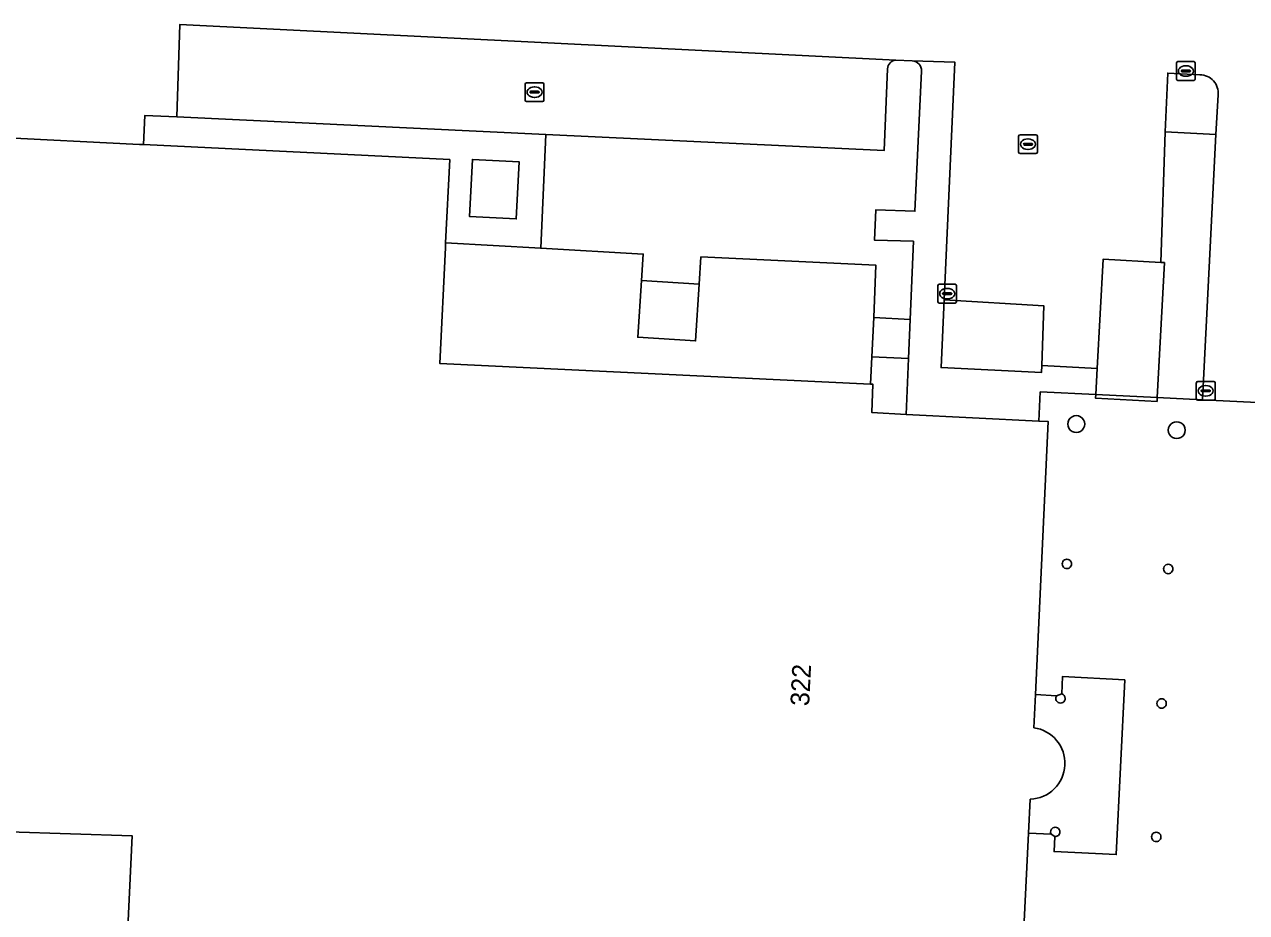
# Model space of a CAD drawing. Extents: x 161090 to 161692, y 379509 to 380907.
# Drawn here: x 161388.6 to 161453.8, y 379714.5 to 379761.9 of the extents above; entities that cross this region are included whole.
import ezdxf

# ---------------------------------------------------------------- set-up
doc = ezdxf.new("R2010")
doc.units = 0
for name, color, linetype in [('IMGEO_Erf', 7, 'Continuous'), ('IMGEO_Groenvoorziening', 7, 'Continuous'), ('IMGEO_Haag', 7, 'Continuous'), ('IMGEO_Hek', 7, 'Continuous'), ('IMGEO_Kolk', 7, 'Continuous'), ('IMGEO_Lage_trafo', 7, 'Continuous'), ('IMGEO_Pand', 7, 'Continuous'), ('IMGEO_Pand_nummerreeks', 7, 'Continuous'), ('IMGEO_Pand_overbouw', 7, 'Continuous'), ('IMGEO_Parkeervlak_gesloten', 7, 'Continuous'), ('IMGEO_Parkeervlak_open', 7, 'Continuous'), ('IMGEO_Rijbaan_lokaal_gesloten', 7, 'Continuous'), ('IMGEO_Rioolput', 7, 'Continuous'), ('IMGEO_Terreindeel_open', 7, 'Continuous'), ('IMGEO_Voetpad_gesloten', 7, 'Continuous'), ('IMGEO_Voetpad_op_trap', 7, 'Continuous'), ('IMGEO_Voetpad_open', 7, 'Continuous')]:
    doc.layers.add(name, color=color, linetype=linetype)

msp = doc.modelspace()

# ---------------------------------------------------------------- linework, layer by layer
at = {"layer": 'IMGEO_Erf'}
msp.add_lwpolyline([(161393.342, 379697.826), (161394.323, 379718.608), (161387.744, 379718.815), (161387.652, 379717.177), (161387.093, 379717.207), (161387.165, 379718.859), (161353.985, 379720.484), (161353.912, 379718.998), (161353.33, 379719.026), (161353.409, 379720.658), (161352.052, 379720.725), (161350.399, 379720.806), (161349.468, 379701.796)], dxfattribs=at)
at = {"layer": 'IMGEO_Groenvoorziening'}
msp.add_lwpolyline([(161451.317, 379759.209), (161449.598, 379759.302), (161449.468, 379756.157), (161452.159, 379756.027), (161452.284, 379758.132)], dxfattribs=at)
msp.add_lwpolyline([(161437.498, 379743.586), (161442.865, 379743.325), (161442.878, 379743.692), (161442.991, 379746.88), (161437.657, 379747.198)], close=True, dxfattribs=at)
msp.add_arc((161451.312, 379758.232), 0.977, 354.11095, 89.72813, dxfattribs=at)
at = {"layer": 'IMGEO_Haag'}
msp.add_lwpolyline([(161451.317, 379759.209), (161449.598, 379759.302), (161449.468, 379756.157), (161452.159, 379756.027), (161452.284, 379758.132)], dxfattribs=at)
msp.add_arc((161451.312, 379758.232), 0.977, 354.11095, 89.72813, dxfattribs=at)
at = {"layer": 'IMGEO_Hek'}
for points in [[(161445.824, 379743.532), (161446.142, 379749.367), (161449.235, 379749.199)], [(161449.235, 379749.199), (161449.419, 379749.189), (161449.04, 379741.982)], [(161445.752, 379742.144), (161445.824, 379743.532)], [(161449.04, 379741.982), (161449.03, 379741.781), (161445.742, 379741.953), (161445.752, 379742.144)]]:
    msp.add_lwpolyline(points, dxfattribs=at)
at = {"layer": 'IMGEO_Kolk'}
for p, q in [((161450.064, 379758.982), (161450.064, 379759.834)), ((161450.139, 379759.908), (161450.991, 379759.908)), ((161451.065, 379759.834), (161451.065, 379758.982)), ((161450.323, 379759.402), (161450.323, 379759.414)), ((161450.761, 379759.365), (161450.363, 379759.365)), ((161450.366, 379759.451), (161450.764, 379759.451)), ((161450.575, 379759.128), (161450.55, 379759.128)), ((161450.552, 379759.688), (161450.577, 379759.688)), ((161450.807, 379759.414), (161450.807, 379759.402)), ((161450.991, 379758.908), (161450.139, 379758.908)), ((161437.4, 379748.029), (161438.252, 379748.029)), ((161437.325, 379747.103), (161437.325, 379747.955)), ((161437.584, 379747.523), (161437.584, 379747.535)), ((161438.022, 379747.486), (161437.624, 379747.486)), ((161437.627, 379747.572), (161438.025, 379747.572)), ((161437.813, 379747.809), (161437.838, 379747.809)), ((161438.068, 379747.535), (161438.068, 379747.523)), ((161438.326, 379747.955), (161438.326, 379747.103)), ((161438.252, 379747.029), (161437.4, 379747.029)), ((161437.836, 379747.249), (161437.811, 379747.249)), ((161451.123, 379741.92), (161451.123, 379742.772)), ((161451.198, 379742.846), (161452.05, 379742.846)), ((161452.124, 379742.772), (161452.124, 379741.92)), ((161451.382, 379742.34), (161451.382, 379742.352)), ((161451.82, 379742.303), (161451.422, 379742.303)), ((161451.425, 379742.389), (161451.823, 379742.389)), ((161451.611, 379742.626), (161451.636, 379742.626)), ((161451.866, 379742.352), (161451.866, 379742.34)), ((161452.05, 379741.846), (161451.198, 379741.846)), ((161451.634, 379742.066), (161451.609, 379742.066))]:
    msp.add_line(p, q, dxfattribs=at)
for points in [[(161450.064, 379758.982), (161450.064, 379759.834)], [(161450.139, 379759.908), (161450.991, 379759.908)], [(161451.065, 379759.834), (161451.065, 379758.982)], [(161450.991, 379758.908), (161450.139, 379758.908)], [(161437.4, 379748.029), (161438.252, 379748.029)], [(161437.325, 379747.103), (161437.325, 379747.955)], [(161438.326, 379747.955), (161438.326, 379747.103)], [(161438.252, 379747.029), (161437.4, 379747.029)], [(161451.123, 379741.92), (161451.123, 379742.772)], [(161451.198, 379742.846), (161452.05, 379742.846)], [(161452.124, 379742.772), (161452.124, 379741.92)], [(161452.05, 379741.846), (161451.198, 379741.846)]]:
    msp.add_lwpolyline(points, dxfattribs=at)
for centre, radius, start, end in [((161450.141, 379759.832), 0.0765, 91.55205, 178.44795), ((161450.141, 379759.832), 0.0765, 91.55205, 178.44795), ((161450.989, 379759.832), 0.0765, 1.55205, 88.44795), ((161450.989, 379759.832), 0.0765, 1.55205, 88.44795), ((161450.363, 379759.411), 0.0403, 85.87752, 175.75265), ((161450.36, 379759.401), 0.0366, 178.93798, 274.71019), ((161450.764, 379759.408), 0.043, 264.86636, 352.45326), ((161450.768, 379759.413), 0.0386, 1.73085, 96.63898), ((161450.141, 379758.984), 0.0765, 181.55205, 268.44795), ((161450.141, 379758.984), 0.0765, 181.55205, 268.44795), ((161450.989, 379758.984), 0.0765, 271.55205, 358.44795), ((161450.989, 379758.984), 0.0765, 271.55205, 358.44795), ((161437.402, 379747.953), 0.0765, 91.55205, 178.44795), ((161437.402, 379747.953), 0.0765, 91.55205, 178.44795), ((161438.25, 379747.953), 0.0765, 1.55205, 88.44795), ((161438.25, 379747.953), 0.0765, 1.55205, 88.44795), ((161437.624, 379747.532), 0.0403, 85.87752, 175.75265), ((161437.621, 379747.522), 0.0366, 178.93798, 274.71019), ((161438.025, 379747.529), 0.043, 264.86636, 352.45326), ((161438.029, 379747.534), 0.0386, 1.73085, 96.63898), ((161437.402, 379747.105), 0.0765, 181.55205, 268.44795), ((161437.402, 379747.105), 0.0765, 181.55205, 268.44795), ((161438.25, 379747.105), 0.0765, 271.55205, 358.44795), ((161438.25, 379747.105), 0.0765, 271.55205, 358.44795), ((161451.2, 379742.77), 0.0765, 91.55205, 178.44795), ((161451.2, 379742.77), 0.0765, 91.55205, 178.44795), ((161452.048, 379742.77), 0.0765, 1.55205, 88.44795), ((161452.048, 379742.77), 0.0765, 1.55205, 88.44795), ((161451.422, 379742.349), 0.0403, 85.87752, 175.75265), ((161451.419, 379742.339), 0.0366, 178.93798, 274.71019), ((161451.823, 379742.346), 0.043, 264.86636, 352.45326), ((161451.827, 379742.351), 0.0386, 1.73085, 96.63898), ((161451.2, 379741.922), 0.0765, 181.55205, 268.44795), ((161451.2, 379741.922), 0.0765, 181.55205, 268.44795), ((161452.048, 379741.922), 0.0765, 271.55205, 358.44795), ((161452.048, 379741.922), 0.0765, 271.55205, 358.44795)]:
    msp.add_arc(centre, radius, start, end, dxfattribs=at)
for centre, major_axis, ratio, start_param, end_param in [((161450.551, 379759.408), (-0.387, 0.002), 0.722429, 4.712389, 7.853982), ((161450.576, 379759.408), (-0.39, 0.002), 0.717154, 1.570796, 4.712389), ((161437.812, 379747.529), (-0.387, 0.002), 0.722429, 4.712389, 7.853982), ((161437.837, 379747.529), (-0.39, 0.002), 0.717154, 1.570796, 4.712389), ((161451.61, 379742.346), (-0.387, 0.002), 0.722429, 4.712389, 7.853982), ((161451.635, 379742.346), (-0.39, 0.002), 0.717154, 1.570796, 4.712389)]:
    msp.add_ellipse(centre, major_axis=major_axis, ratio=ratio, start_param=start_param, end_param=end_param, dxfattribs=at)
at = {"layer": 'IMGEO_Lage_trafo'}
msp.add_lwpolyline([(161414.825, 379751.52), (161414.976, 379754.567), (161412.49, 379754.691), (161412.338, 379751.644)], close=True, dxfattribs=at)
at = {"layer": 'IMGEO_Pand'}
for points in [[(161442.449, 379724.367), (161442.537, 379726.14), (161443.22, 379740.706), (161442.709, 379740.733), (161435.636, 379741.089), (161433.806, 379741.181), (161433.864, 379742.696), (161433.729, 379742.702), (161410.743, 379743.807), (161411.046, 379750), (161411.058, 379750.236), (161411.276, 379754.683), (161394.932, 379755.485), (161394.714, 379755.496), (161386.953, 379755.876)], [(161443.94, 379726.177), (161443.663, 379726.071)], [(161349.468, 379701.796), (161350.399, 379720.806), (161352.052, 379720.725), (161353.409, 379720.658), (161353.33, 379719.026), (161353.912, 379718.998), (161353.985, 379720.484), (161387.165, 379718.859), (161387.093, 379717.207), (161387.652, 379717.177), (161387.744, 379718.815), (161394.323, 379718.608), (161393.342, 379697.826)], [(161441.094, 379697.013), (161442.171, 379718.753), (161442.261, 379720.561)], [(161443.371, 379718.693), (161443.57, 379718.564)]]:
    msp.add_lwpolyline(points, dxfattribs=at)
for centre, radius, start, end in [((161444.716, 379740.571), 0.45, 119.97301, 240.02699), ((161444.717, 379740.572), 0.449, 359.89963, 120.191), ((161444.716, 379740.571), 0.45, 240.00001, 0.03673), ((161450.076, 379740.247), 0.45, 119.97301, 240.02699), ((161450.076, 379740.247), 0.45, 0.09067, 119.99996), ((161450.076, 379740.248), 0.45, 240.00001, 0.03673), ((161444.217, 379733.109), 0.25, 119.99835, 240.00165), ((161444.217, 379733.109), 0.25, 0.11618, 119.99993), ((161444.217, 379733.109), 0.25, 240.00006, 0.11301), ((161449.622, 379732.84), 0.25, 119.99835, 240.00165), ((161449.623, 379732.842), 0.249, 359.7724, 120.34371), ((161449.622, 379732.84), 0.25, 240.00006, 0.11301), ((161443.872, 379725.936), 0.249, 147.03095, 240.19501), ((161443.873, 379725.937), 0.25, 240.00006, 0.11301), ((161443.874, 379725.937), 0.249, 359.97735, 74.67369), ((161449.273, 379725.665), 0.25, 119.99835, 240.00165), ((161449.273, 379725.666), 0.249, 359.62198, 120.13222), ((161449.272, 379725.664), 0.25, 240.06628, 359.95003), ((161442.199, 379722.472), 1.912, 271.87035, 82.47391), ((161443.591, 379718.813), 0.251, 119.98167, 208.53214), ((161443.59, 379718.812), 0.251, 0.23077, 119.65616), ((161443.591, 379718.813), 0.25, 265.22341, 359.93138), ((161448.986, 379718.543), 0.25, 119.99835, 240.00165), ((161448.986, 379718.543), 0.25, 359.88699, 119.99994), ((161448.987, 379718.542), 0.249, 239.65629, 0.2276)]:
    msp.add_arc(centre, radius, start, end, dxfattribs=at)
at = {"layer": 'IMGEO_Pand_overbouw'}
for points in [[(161442.795, 379742.289), (161442.709, 379740.733), (161443.22, 379740.706), (161442.537, 379726.14), (161442.449, 379724.367)], [(161460.755, 379740.055), (161460.82, 379741.402), (161459.765, 379741.454), (161459.115, 379741.486), (161451.449, 379741.864), (161449.04, 379741.982), (161445.752, 379742.144), (161442.795, 379742.289)], [(161442.261, 379720.561), (161442.171, 379718.753), (161441.094, 379697.013), (161431.78, 379697.442), (161431.696, 379695.994), (161441.029, 379695.563), (161449.168, 379695.186), (161456.81, 379694.832), (161465.062, 379694.45), (161465.67, 379694.422), (161467.944, 379740.954), (161467.337, 379740.979), (161466.381, 379741.018), (161466.333, 379739.73)]]:
    msp.add_lwpolyline(points, dxfattribs=at)
msp.add_arc((161442.199, 379722.472), 1.912, 271.87035, 82.47391, dxfattribs=at)
at = {"layer": 'IMGEO_Parkeervlak_gesloten'}
msp.add_lwpolyline([(161435.089, 379759.99), (161396.874, 379761.893), (161396.715, 379756.957), (161416.396, 379756.022), (161434.456, 379755.166), (161434.643, 379759.524)], dxfattribs=at)
msp.add_arc((161435.127, 379759.507), 0.484, 94.48379, 178.02878, dxfattribs=at)
at = {"layer": 'IMGEO_Parkeervlak_open'}
msp.add_lwpolyline([(161460.755, 379740.055), (161460.82, 379741.402), (161459.765, 379741.454), (161459.115, 379741.486), (161451.449, 379741.864), (161449.04, 379741.982), (161449.03, 379741.781), (161445.742, 379741.953), (161445.752, 379742.144), (161442.795, 379742.289), (161442.709, 379740.733), (161443.22, 379740.706), (161442.537, 379726.14), (161443.663, 379726.071), (161443.94, 379726.177), (161443.986, 379727.11), (161447.301, 379726.922), (161446.847, 379717.599), (161443.531, 379717.764), (161443.57, 379718.564), (161443.371, 379718.693), (161442.171, 379718.753), (161441.094, 379697.013)], dxfattribs=at)
for centre, radius, start, end in [((161444.716, 379740.571), 0.45, 119.97301, 240.02699), ((161444.717, 379740.572), 0.449, 359.89963, 120.191), ((161444.716, 379740.571), 0.45, 240.00001, 0.03673), ((161450.076, 379740.247), 0.45, 119.97301, 240.02699), ((161450.076, 379740.247), 0.45, 0.09067, 119.99996), ((161450.076, 379740.248), 0.45, 240.00001, 0.03673), ((161444.217, 379733.109), 0.25, 119.99835, 240.00165), ((161444.217, 379733.109), 0.25, 0.11618, 119.99993), ((161444.217, 379733.109), 0.25, 240.00006, 0.11301), ((161449.622, 379732.84), 0.25, 119.99835, 240.00165), ((161449.623, 379732.842), 0.249, 359.7724, 120.34371), ((161449.622, 379732.84), 0.25, 240.00006, 0.11301), ((161449.273, 379725.665), 0.25, 119.99835, 240.00165), ((161449.273, 379725.666), 0.249, 359.62198, 120.13222), ((161449.272, 379725.664), 0.25, 240.06628, 359.95003), ((161448.986, 379718.543), 0.25, 119.99835, 240.00165), ((161448.986, 379718.543), 0.25, 359.88699, 119.99994), ((161448.987, 379718.542), 0.249, 239.65629, 0.2276)]:
    msp.add_arc(centre, radius, start, end, dxfattribs=at)
at = {"layer": 'IMGEO_Rijbaan_lokaal_gesloten'}
for points in [[(161387.133, 379760.372), (161386.824, 379755.883), (161386.953, 379755.876), (161394.714, 379755.496), (161394.932, 379755.485), (161395.008, 379757.039), (161396.715, 379756.957), (161396.874, 379761.893), (161435.089, 379759.99), (161435.965, 379759.96), (161438.228, 379759.883), (161437.657, 379747.198), (161442.991, 379746.88), (161442.878, 379743.692), (161445.824, 379743.532), (161446.142, 379749.367), (161449.235, 379749.199), (161449.468, 379756.157), (161449.598, 379759.302), (161451.317, 379759.209)], [(161452.284, 379758.132), (161452.159, 379756.027), (161451.449, 379741.864), (161459.115, 379741.486), (161459.778, 379755.552), (161459.86, 379756.999)]]:
    msp.add_lwpolyline(points, dxfattribs=at)
msp.add_arc((161451.312, 379758.232), 0.977, 354.11095, 89.72813, dxfattribs=at)
at = {"layer": 'IMGEO_Rioolput'}
for p, q in [((161415.302, 379757.856), (161415.302, 379758.708)), ((161415.377, 379758.782), (161416.229, 379758.782)), ((161415.79, 379758.562), (161415.815, 379758.562)), ((161416.303, 379758.708), (161416.303, 379757.856)), ((161416.229, 379757.782), (161415.377, 379757.782)), ((161415.561, 379758.276), (161415.561, 379758.288)), ((161415.999, 379758.239), (161415.601, 379758.239)), ((161415.604, 379758.325), (161416.002, 379758.325)), ((161415.813, 379758.002), (161415.788, 379758.002)), ((161416.045, 379758.288), (161416.045, 379758.276)), ((161441.637, 379755.077), (161441.637, 379755.929)), ((161441.712, 379756.003), (161442.564, 379756.003)), ((161442.638, 379755.929), (161442.638, 379755.077)), ((161441.896, 379755.497), (161441.896, 379755.509)), ((161442.334, 379755.46), (161441.936, 379755.46)), ((161441.939, 379755.546), (161442.337, 379755.546)), ((161442.148, 379755.223), (161442.123, 379755.223)), ((161442.125, 379755.783), (161442.15, 379755.783)), ((161442.38, 379755.509), (161442.38, 379755.497)), ((161442.564, 379755.003), (161441.712, 379755.003))]:
    msp.add_line(p, q, dxfattribs=at)
for points in [[(161415.302, 379757.856), (161415.302, 379758.708)], [(161415.377, 379758.782), (161416.229, 379758.782)], [(161416.303, 379758.708), (161416.303, 379757.856)], [(161416.229, 379757.782), (161415.377, 379757.782)], [(161441.637, 379755.077), (161441.637, 379755.929)], [(161441.712, 379756.003), (161442.564, 379756.003)], [(161442.638, 379755.929), (161442.638, 379755.077)], [(161442.564, 379755.003), (161441.712, 379755.003)]]:
    msp.add_lwpolyline(points, dxfattribs=at)
for centre, radius, start, end in [((161415.379, 379758.706), 0.0765, 91.55205, 178.44795), ((161415.379, 379758.706), 0.0765, 91.55205, 178.44795), ((161416.227, 379758.706), 0.0765, 1.55205, 88.44795), ((161416.227, 379758.706), 0.0765, 1.55205, 88.44795), ((161415.379, 379757.858), 0.0765, 181.55205, 268.44795), ((161415.379, 379757.858), 0.0765, 181.55205, 268.44795), ((161415.601, 379758.285), 0.0403, 85.87752, 175.75265), ((161415.598, 379758.275), 0.0366, 178.93798, 274.71019), ((161416.002, 379758.282), 0.043, 264.86636, 352.45326), ((161416.006, 379758.287), 0.0386, 1.73085, 96.63898), ((161416.227, 379757.858), 0.0765, 271.55205, 358.44795), ((161416.227, 379757.858), 0.0765, 271.55205, 358.44795), ((161441.714, 379755.927), 0.0765, 91.55205, 178.44795), ((161441.714, 379755.927), 0.0765, 91.55205, 178.44795), ((161442.562, 379755.927), 0.0765, 1.55205, 88.44795), ((161442.562, 379755.927), 0.0765, 1.55205, 88.44795), ((161441.936, 379755.506), 0.0403, 85.87752, 175.75265), ((161441.933, 379755.496), 0.0366, 178.93798, 274.71019), ((161442.337, 379755.503), 0.043, 264.86636, 352.45326), ((161442.341, 379755.508), 0.0386, 1.73085, 96.63898), ((161441.714, 379755.079), 0.0765, 181.55205, 268.44795), ((161441.714, 379755.079), 0.0765, 181.55205, 268.44795), ((161442.562, 379755.079), 0.0765, 271.55205, 358.44795), ((161442.562, 379755.079), 0.0765, 271.55205, 358.44795)]:
    msp.add_arc(centre, radius, start, end, dxfattribs=at)
for centre, major_axis, ratio, start_param, end_param in [((161415.789, 379758.282), (-0.387, 0.002), 0.722429, 4.712389, 7.853982), ((161415.814, 379758.282), (-0.39, 0.002), 0.717154, 1.570796, 4.712389), ((161442.124, 379755.503), (-0.387, 0.002), 0.722429, 4.712389, 7.853982), ((161442.149, 379755.503), (-0.39, 0.002), 0.717154, 1.570796, 4.712389)]:
    msp.add_ellipse(centre, major_axis=major_axis, ratio=ratio, start_param=start_param, end_param=end_param, dxfattribs=at)
at = {"layer": 'IMGEO_Terreindeel_open'}
msp.add_lwpolyline([(161449.419, 379749.189), (161449.235, 379749.199), (161446.142, 379749.367), (161445.824, 379743.532), (161445.752, 379742.144), (161445.742, 379741.953), (161449.03, 379741.781), (161449.04, 379741.982)], close=True, dxfattribs=at)
at = {"layer": 'IMGEO_Voetpad_gesloten'}
for points in [[(161416.396, 379756.022), (161396.715, 379756.957), (161395.008, 379757.039), (161394.932, 379755.485), (161411.276, 379754.683), (161411.058, 379750.236), (161416.137, 379749.952)], [(161412.49, 379754.691), (161414.976, 379754.567), (161414.825, 379751.52), (161412.338, 379751.644)]]:
    msp.add_lwpolyline(points, close=True, dxfattribs=at)
at = {"layer": 'IMGEO_Voetpad_op_trap'}
msp.add_lwpolyline([(161424.588, 379748.036), (161421.514, 379748.238), (161421.31, 379745.208), (161424.393, 379745.011)], close=True, dxfattribs=at)
at = {"layer": 'IMGEO_Voetpad_open'}
for points in [[(161436.462, 379759.406), (161436.102, 379751.931), (161434.024, 379752.011), (161433.946, 379750.387), (161436.025, 379750.33), (161435.849, 379746.157), (161435.761, 379744.07), (161435.636, 379741.089), (161442.709, 379740.733), (161442.795, 379742.289), (161445.752, 379742.144), (161445.824, 379743.532), (161442.878, 379743.692), (161442.865, 379743.325), (161437.498, 379743.586), (161437.657, 379747.198), (161438.228, 379759.883)], [(161435.965, 379759.96), (161435.089, 379759.99)], [(161438.228, 379759.883), (161435.965, 379759.96)], [(161434.643, 379759.524), (161434.456, 379755.166), (161416.396, 379756.022), (161416.137, 379749.952), (161421.608, 379749.645), (161421.514, 379748.238), (161424.588, 379748.036), (161424.682, 379749.493), (161434.019, 379749.044), (161433.912, 379746.249), (161435.849, 379746.157), (161436.025, 379750.33), (161433.946, 379750.387), (161434.024, 379752.011)], [(161434.024, 379752.011), (161436.102, 379751.931), (161436.462, 379759.406)], [(161443.57, 379718.564), (161443.531, 379717.764), (161446.847, 379717.599), (161447.301, 379726.922), (161443.986, 379727.11), (161443.94, 379726.177)], [(161443.663, 379726.071), (161442.537, 379726.14), (161442.449, 379724.367)], [(161442.261, 379720.561), (161442.171, 379718.753), (161443.371, 379718.693)]]:
    msp.add_lwpolyline(points, dxfattribs=at)
for points in [[(161451.449, 379741.864), (161452.159, 379756.027), (161449.468, 379756.157), (161449.235, 379749.199), (161449.419, 379749.189), (161449.04, 379741.982)], [(161421.514, 379748.238), (161421.608, 379749.645), (161416.137, 379749.952), (161411.058, 379750.236), (161411.046, 379750), (161410.743, 379743.807), (161433.729, 379742.702), (161433.808, 379744.163), (161433.912, 379746.249), (161434.019, 379749.044), (161424.682, 379749.493), (161424.588, 379748.036), (161424.393, 379745.011), (161421.31, 379745.208)], [(161435.761, 379744.07), (161435.849, 379746.157), (161433.912, 379746.249), (161433.808, 379744.163)], [(161433.864, 379742.696), (161433.806, 379741.181), (161435.636, 379741.089), (161435.761, 379744.07), (161433.808, 379744.163), (161433.729, 379742.702)]]:
    msp.add_lwpolyline(points, close=True, dxfattribs=at)
for centre, radius, start, end in [((161435.127, 379759.507), 0.484, 94.48379, 178.02878), ((161435.921, 379759.421), 0.541, 358.42308, 85.36823), ((161435.921, 379759.421), 0.541, 358.42308, 85.36823), ((161443.872, 379725.936), 0.249, 147.03095, 240.19501), ((161443.873, 379725.937), 0.25, 240.00006, 0.11301), ((161443.874, 379725.937), 0.249, 359.97735, 74.67369), ((161442.199, 379722.472), 1.912, 271.87035, 82.47391), ((161443.591, 379718.813), 0.251, 119.98167, 208.53214), ((161443.59, 379718.812), 0.251, 0.23077, 119.65616), ((161443.591, 379718.813), 0.25, 265.22341, 359.93138)]:
    msp.add_arc(centre, radius, start, end, dxfattribs=at)

# ---------------------------------------------------------------- texts
at = {"layer": 'IMGEO_Pand_nummerreeks'}
msp.add_text('322', height=1, rotation=87.12969, dxfattribs=at).set_placement((161430.454, 379725.509))

doc.saveas('drawing.dxf')
